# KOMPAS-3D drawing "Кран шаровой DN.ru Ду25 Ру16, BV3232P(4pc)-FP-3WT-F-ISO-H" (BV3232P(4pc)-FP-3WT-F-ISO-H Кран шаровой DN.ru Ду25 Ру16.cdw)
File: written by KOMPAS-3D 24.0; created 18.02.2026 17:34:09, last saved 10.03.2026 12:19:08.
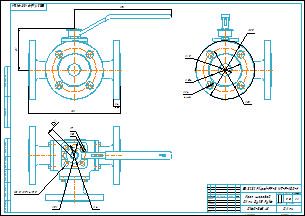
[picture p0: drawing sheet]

Document properties: Автор: R2D2; Форматы листов документа: A2; Полное имя файла: BV3232P(4pc)-FP-3WT-F-ISO-H Кран шаровой DN.ru Ду25 Ру16.m3d; Масса: 5.6; Наименование: Кран шаровой DN.ru Ду25 Ру16; Количество листов документа: 1; Примечание: D160-36348

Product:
- Part/product: Кран шаровой DN.ru Ду25 Ру16  | designation BV3232P(4pc)-FP-3WT-F-ISO-H
    Масса: 5.6
    Раздел спецификации: Прочие изделия
    Примечание: D160-36348

Views: Вид 1, Спереди, Проекционный вид 2
Referenced files in E:\Работа\Зайцев\BV3232P(4pc)-FP-3WL-F-ISO-H Кран шаровой DN.ru Ду15-100 Ру16\DN25\: BV3232P(4pc)-FP-3WL-F-ISO-H Кран шаровой DN.ru Ду25 Ру16.m3d
Referenced files in E:\Работа\Зайцев\BV3232P(4pc)-FP-3WT-F-ISO-H Кран шаровой DN.ru Ду15-100 Ру16\DN25\: BV3232P(4pc)-FP-3WT-F-ISO-H Кран шаровой DN.ru Ду25 Ру16.m3d
Referenced files in E:\Работа\Зайцев\Для компаса\: чертеж DN.ru А3.cdt
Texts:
  BV3232P(4pc)-FP-3WT-F-ISO-H
  чертеж DN.ru А3.cdt
  Кран шаровой
  DN.ru Ду25 Ру16
  Кран шаровой DN.ru Ду25 Ру16
  BV3232P(4pc)-FP-3WT-F-ISO-H Кран шаровой DN.ru Ду25 Ру16
Dimensions and other numbers on the sheet: 0; 3; 2; 4; 180; 14; 82; 190; 115; 85; 64; 25; 4 отв.; 1:1; 1; 5,6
